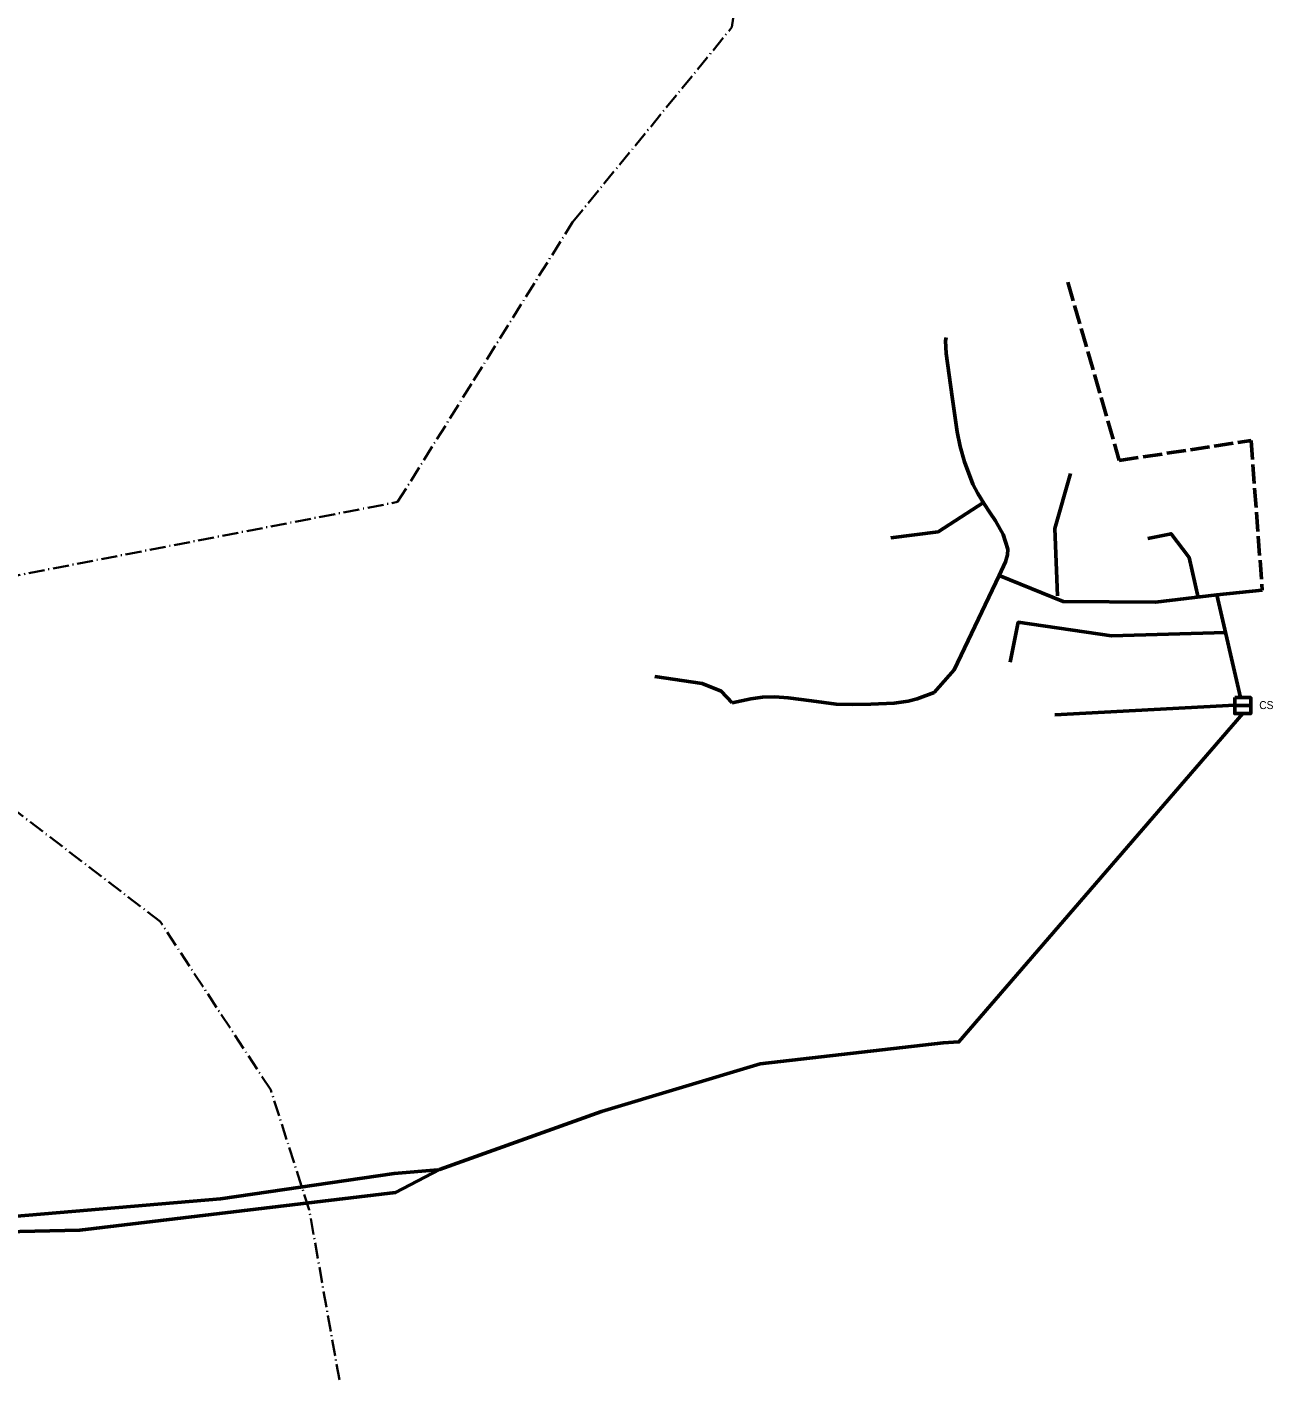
# Model space of a CAD drawing. Extents: x -650270 to -643402, y -1075206 to -1066807.
# Drawn here: x -644959 to -643402, y -1070961 to -1069270 of the extents above; entities that cross this region are included whole.
import ezdxf

# ---------------------------------------------------------------- set-up
doc = ezdxf.new("R2010")
doc.units = 0
doc.header["$LTSCALE"] = 4
doc.linetypes.add('DOT_DASHED', pattern=[7.7, 5, -1.2, 0.3, -1.2])
doc.linetypes.add('LONG_DASHED', pattern=[7.5, 6, -1.5])
for name, color, linetype, lineweight in [('17', 7, 'DOT_DASHED', 35), ('4', 7, 'Continuous', 53), ('41', 7, 'Continuous', 25), ('48', 7, 'Continuous', 53), ('50', 7, 'Continuous', 53), ('51', 7, 'Continuous', 53)]:
    doc.layers.add(name, color=color, linetype=linetype, lineweight=lineweight)
doc.layers.add('42', color=7, linetype='Continuous')

msp = doc.modelspace()

# ---------------------------------------------------------------- linework, layer by layer
at = {"layer": '17'}
for points in [[(-644568.435, -1070960.552), (-644606.234, -1070747.935), (-644654.246, -1070597.895), (-644792.283, -1070387.84), (-645046.599, -1070192.79), (-645228.623, -1070004.752), (-645232.28, -1069980.924), (-645262.713, -1069836.388), (-645315.002, -1069657.333), (-645409.031, -1069473.75), (-645471.738, -1069397.026), (-645547.224, -1069323.801), (-645594.94, -1069288.511), (-645620.197, -1069220.915), (-645784.301, -1069029.743), (-645967.439, -1068809.81), (-646082.481, -1068583.109), (-646148.037, -1068369.943), (-646184.835, -1068097.563), (-646183.288, -1067867.427)], [(-645228.623, -1070004.752), (-644495.665, -1069863.346), (-644400.764, -1069711.504), (-644277.073, -1069513.597), (-644078.1, -1069270.213), (-644047.301, -1069043.419)]]:
    msp.add_lwpolyline(points, dxfattribs=at)
at = {"layer": '4'}
msp.add_lwpolyline([(-644445.454, -1070697.774), (-644500.038, -1070702.585), (-644716.965, -1070734.034), (-644976.129, -1070756.486), (-645086.887, -1070754.876), (-645202.78, -1070753.267), (-645305.795, -1070754.34), (-645369.783, -1070785.657), (-645445.374, -1070804.496)], dxfattribs=at)
at = {"layer": '41', "lineweight": 53}
msp.add_line((-643450.027, -1070117.812), (-643430.027, -1070117.812), dxfattribs=at)
msp.add_lwpolyline([(-643450.027, -1070107.812), (-643430.027, -1070107.812), (-643430.027, -1070127.812), (-643450.027, -1070127.812)], close=True, dxfattribs=at)
at = {"layer": '48', "linetype": 'LONG_DASHED'}
msp.add_line((-643658.395, -1069588.818), (-643594.181, -1069811.599), dxfattribs=at)
at = {"layer": '48'}
for p, q in [((-643415.602, -1069973.457), (-643472.434, -1069979.54)), ((-643674.528, -1070129.34), (-643450.027, -1070117.352))]:
    msp.add_line(p, q, dxfattribs=at)
for points in [[(-643810.627, -1069657.665), (-643811.385, -1069662.021), (-643810.389, -1069677.722), (-643802.82, -1069731.886), (-643796.749, -1069775.852), (-643792.823, -1069793.926), (-643787.529, -1069813.369), (-643777.123, -1069840.937), (-643771.098, -1069852.895), (-643763.019, -1069865.538), (-643755.762, -1069876.675), (-643748.825, -1069886.853), (-643739.057, -1069904.105), (-643733.398, -1069922.453), (-643733.672, -1069929.3), (-643736.136, -1069938.154), (-643744.205, -1069955.268)], [(-643655.213, -1069827.906), (-643674.851, -1069896.398), (-643671.436, -1069980.856)], [(-643879.717, -1069908.04), (-643820.566, -1069900.574), (-643763.713, -1069863.82)], [(-643558.728, -1069909.08), (-643529.51, -1069903.099), (-643506.883, -1069932.918), (-643495.544, -1069982.565)], [(-643825.501, -1070101.354), (-643800.43, -1070073.069), (-643744.205, -1069955.268)], [(-643744.205, -1069955.268), (-643664.391, -1069987.784), (-643548.771, -1069988.527), (-643472.434, -1069979.54), (-643442.585, -1070107.812)], [(-643730.467, -1070063.614), (-643720.412, -1070013.703), (-643603.827, -1070030.469), (-643461.54, -1070026.354)], [(-644174.372, -1070081.528), (-644115.344, -1070090.018), (-644091.49, -1070099.721), (-644077.983, -1070114.354)], [(-644077.983, -1070114.354), (-644054.663, -1070109.432), (-644040.027, -1070107.201), (-644024.686, -1070106.729), (-644007.981, -1070107.962), (-643978.816, -1070112.024), (-643947.688, -1070115.858), (-643927.411, -1070116.568), (-643904.548, -1070116.112), (-643875.543, -1070114.925), (-643858.108, -1070112.46), (-643846.88, -1070109.266), (-643825.501, -1070101.354)]]:
    msp.add_lwpolyline(points, dxfattribs=at)
at = {"layer": '48', "linetype": 'LONG_DASHED'}
msp.add_lwpolyline([(-643594.181, -1069811.599), (-643429.636, -1069786.459), (-643415.602, -1069973.457)], dxfattribs=at)
at = {"layer": '50'}
msp.add_lwpolyline([(-643439.868, -1070127.812), (-643794.576, -1070538.041), (-643814.314, -1070539.274), (-644042.664, -1070565.642), (-644241.161, -1070625.072), (-644443.224, -1070697.577)], dxfattribs=at)
at = {"layer": '51'}
msp.add_lwpolyline([(-644443.224, -1070697.577), (-644498.43, -1070726.295), (-644892.766, -1070773.328), (-645079.923, -1070777.683), (-645305.382, -1070779.425), (-645420.722, -1070830.204), (-645445.374, -1070804.496)], dxfattribs=at)

# ---------------------------------------------------------------- texts
at = {"layer": '42', "width": 0.95}
msp.add_text('CS', height=10, dxfattribs=at).set_placement((-643419.321, -1070122.194))

doc.saveas('drawing.dxf')
